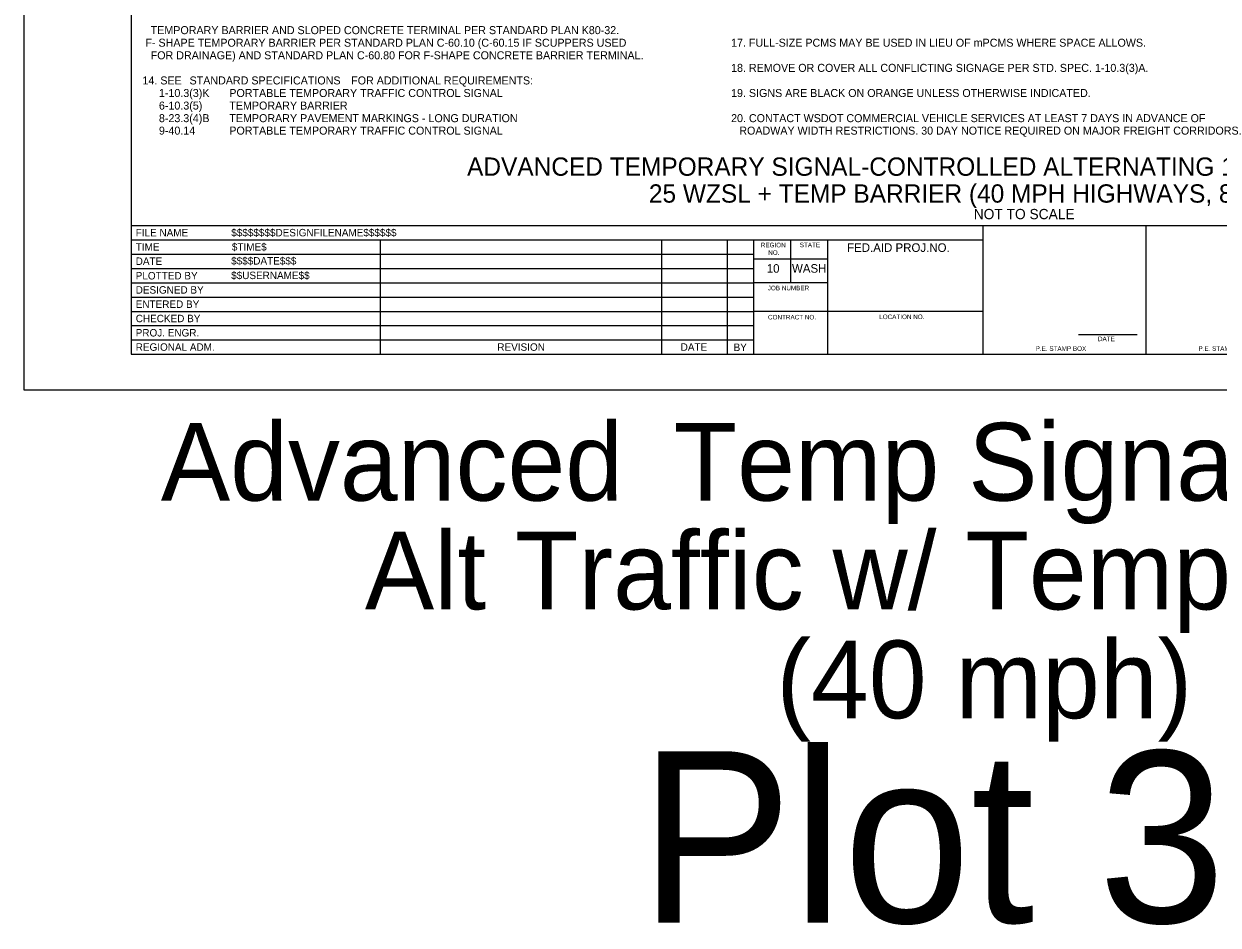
# Model space of a CAD drawing. Extents: x 99982 to 100176, y 99905 to 100011.
# Drawn here: x 100019.06 to 100029.51, y 99905.01 to 99912.89 of the extents above; entities that cross this region are included whole.
import ezdxf

# ---------------------------------------------------------------- set-up
doc = ezdxf.new("R2010")
doc.units = 0
for name, color, linetype in [('SH_DE_DetailHeading1Text', 7, 'Continuous'), ('SH_GI_GeneralNotesBodyText', 7, 'Continuous'), ('SH_GI_PlotLimits', 7, 'Continuous'), ('SH_GI_SheetBorder', 7, 'Continuous'), ('SH_GI_SheetLocationText', 7, 'Continuous'), ('SH_GI_SheetTextInCells', 7, 'Continuous'), ('SH_GI_TitleBlockText', 7, 'Continuous')]:
    doc.layers.add(name, color=color, linetype=linetype)

msp = doc.modelspace()

# ---------------------------------------------------------------- linework, layer by layer
at = {"layer": 'SH_GI_PlotLimits'}
msp.add_lwpolyline([(100019.062, 99909.687), (100036.062, 99909.687), (100036.062, 99920.687), (100019.062, 99920.687)], close=True, dxfattribs=at)
at = {"layer": 'SH_GI_SheetBorder'}
for p, q in [((100020, 99920.375), (100020, 99910)), ((100020, 99911.126), (100035.75, 99911.126)), ((100027.457, 99910), (100027.457, 99911.126)), ((100028.883, 99910), (100028.883, 99911.126)), ((100020, 99911.001), (100027.457, 99911.001)), ((100022.179, 99911.001), (100022.179, 99910)), ((100024.641, 99911.001), (100024.641, 99910)), ((100025.216, 99911.001), (100025.216, 99910)), ((100025.445, 99911.001), (100025.445, 99910)), ((100025.772, 99910.625), (100025.772, 99911.001)), ((100026.096, 99910), (100026.096, 99911.001)), ((100020, 99910.876), (100022.182, 99910.876)), ((100022.182, 99910.876), (100025.447, 99910.876)), ((100026.096, 99910.831), (100025.447, 99910.831)), ((100020, 99910.751), (100022.182, 99910.751)), ((100022.182, 99910.751), (100025.447, 99910.751)), ((100020, 99910.625), (100025.447, 99910.625)), ((100026.096, 99910.625), (100025.447, 99910.625)), ((100020, 99910.5), (100025.447, 99910.5)), ((100020, 99910.375), (100025.447, 99910.375)), ((100027.457, 99910.375), (100025.447, 99910.375)), ((100020, 99910.25), (100025.447, 99910.25)), ((100020, 99910.125), (100025.447, 99910.125)), ((100028.29, 99910.173), (100028.802, 99910.173)), ((100020, 99910), (100035.75, 99910))]:
    msp.add_line(p, q, dxfattribs=at)

# ---------------------------------------------------------------- texts
at = {"layer": 'SH_DE_DetailHeading1Text'}
for s, height, p in [('ADVANCED TEMPORARY SIGNAL-CONTROLLED ALTERNATING 1-LANE, 2-WAY TRAFFIC', 0.16, (100022.94, 99911.561)), ('25 WZSL + TEMP BARRIER (40 MPH HIGHWAYS, 8+ DAYS)', 0.16, (100024.531, 99911.326)), ('NOT TO SCALE', 0.09, (100027.373, 99911.181))]:
    msp.add_text(s, height=height, rotation=360, dxfattribs=at).set_placement(p)
at = {"layer": 'SH_GI_GeneralNotesBodyText'}
for s, p in [('TEMPORARY BARRIER AND SLOPED CONCRETE TERMINAL PER STANDARD PLAN K80-32.', (100020.172, 99912.8)), (' F- SHAPE TEMPORARY BARRIER PER STANDARD PLAN C-60.10 (C-60.15 IF SCUPPERS USED ', (100020.1, 99912.69)), ('17. FULL-SIZE PCMS MAY BE USED IN LIEU OF mPCMS WHERE SPACE ALLOWS.', (100025.25, 99912.69)), ('FOR DRAINAGE) AND STANDARD PLAN C-60.80 FOR F-SHAPE CONCRETE BARRIER TERMINAL.', (100020.172, 99912.58)), ('18. REMOVE OR COVER ALL CONFLICTING SIGNAGE PER STD. SPEC. 1-10.3(3)A. ', (100025.25, 99912.47)), ('14. SEE ', (100020.1, 99912.36)), ('STANDARD SPECIFICATIONS', (100020.512, 99912.36)), (' FOR ADDITIONAL REQUIREMENTS:', (100021.9, 99912.36)), ('1-10.3(3)K', (100020.244, 99912.25)), ('PORTABLE TEMPORARY TRAFFIC CONTROL SIGNAL', (100020.86, 99912.25)), ('19. SIGNS ARE BLACK ON ORANGE UNLESS OTHERWISE INDICATED.', (100025.25, 99912.25)), ('6-10.3(5)', (100020.244, 99912.14)), ('TEMPORARY BARRIER', (100020.86, 99912.14)), ('8-23.3(4)B', (100020.244, 99912.03)), ('TEMPORARY PAVEMENT MARKINGS - LONG DURATION', (100020.86, 99912.03)), ('20. CONTACT WSDOT COMMERCIAL VEHICLE SERVICES AT LEAST 7 DAYS IN ADVANCE OF ', (100025.25, 99912.03)), ('9-40.14', (100020.244, 99911.921)), ('PORTABLE TEMPORARY TRAFFIC CONTROL SIGNAL', (100020.86, 99911.921)), ('ROADWAY WIDTH RESTRICTIONS. 30 DAY NOTICE REQUIRED ON MAJOR FREIGHT CORRIDORS.', (100025.322, 99911.921))]:
    msp.add_text(s, height=0.07, rotation=360, dxfattribs=at).set_placement(p)
at = {"layer": 'SH_GI_SheetLocationText'}
for s, height, p in [('Advanced', 0.68, (100020.261, 99908.719)), (' Temp Signal-Controlled', 0.68, (100024.495, 99908.719)), ('Alt Traffic w/ Temp Barrier', 0.68, (100022.046, 99907.767)), (' (40 mph)', 0.68, (100025.394, 99906.815)), ('Plot 32', 1.5, (100024.448, 99905.027))]:
    msp.add_text(s, height=height, dxfattribs=at).set_placement(p)
at = {"layer": 'SH_GI_SheetTextInCells'}
for s, height, p in [('FILE NAME', 0.0651, (100020.041, 99911.031)), ('TIME', 0.0651, (100020.041, 99910.906)), ('REGION', 0.04, (100025.51, 99910.935)), ('STATE', 0.04, (100025.851, 99910.936)), ('FED.AID PROJ.NO.', 0.07506, (100026.265, 99910.895)), ('NO.', 0.04, (100025.575, 99910.869)), ('DATE', 0.0651, (100020.041, 99910.781)), ('10', 0.0751, (100025.562, 99910.713)), ('WASH', 0.0751, (100025.783, 99910.713)), ('PLOTTED BY', 0.0651, (100020.041, 99910.654)), ('DESIGNED BY', 0.06505, (100020.041, 99910.53)), ('JOB NUMBER', 0.04, (100025.571, 99910.559)), ('ENTERED BY', 0.0651, (100020.041, 99910.405)), ('CHECKED BY', 0.0651, (100020.041, 99910.28)), ('CONTRACT NO.', 0.04003, (100025.573, 99910.304)), ('LOCATION NO.', 0.04003, (100026.546, 99910.307)), ('PROJ. ENGR.', 0.06505, (100020.041, 99910.155)), ('DATE', 0.04, (100028.46, 99910.114)), ('REGIONAL ADM.', 0.06505, (100020.041, 99910.03)), ('REVISION', 0.0651, (100023.205, 99910.03)), ('DATE', 0.0651, (100024.809, 99910.03)), ('BY', 0.0651, (100025.272, 99910.028)), ('P.E. STAMP BOX', 0.04003, (100027.915, 99910.029)), ('P.E. STAMP BOX', 0.04003, (100029.339, 99910.029))]:
    msp.add_text(s, height=height, dxfattribs=at).set_placement(p)
at = {"layer": 'SH_GI_TitleBlockText'}
for s, height, p in [('$$$$$$$$DESIGNFILENAME$$$$$$', 0.06505, (100020.877, 99911.031)), ('$TIME$', 0.0651, (100020.882, 99910.906)), ('$$$$DATE$$$', 0.06505, (100020.876, 99910.784)), ('$$USERNAME$$', 0.06505, (100020.876, 99910.657))]:
    msp.add_text(s, height=height, dxfattribs=at).set_placement(p)

doc.saveas('drawing.dxf')
